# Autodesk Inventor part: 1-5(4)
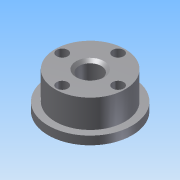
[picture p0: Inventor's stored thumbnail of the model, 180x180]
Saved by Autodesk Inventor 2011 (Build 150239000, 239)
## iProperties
Created: 2014-02
Part Number: 1-5(4)
Document SubType Name: Modeling
Designer: Administrator
Density: 1 g/cm^3
Author: Administrator
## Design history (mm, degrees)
sketch "草图1"
  geometry: C1 r 15 at (0, 0); 1 further point
  constraints: 1 centre point, 1 coincident
  dimensions: "d0" = 30 diameter of C1
extrude "拉伸1" new body sketch "草图1" distance "d1" = 3; taper "d2" = 0 deg
sketch "草图2"
  geometry: C1 r 15 at (0, 0) reference; C2 r 12.5 at (0, 0)
  constraints: 1 centre point, 1 coincident
  dimensions: "d3" = 25 diameter of C2
extrude "拉伸2" join sketch "草图2" distance "d4" = 10; taper "d5" = 0 deg
sketch "草图3"
  geometry: C1 r 12.5 at (0, 0) reference; C2 r 4 at (0, 0)
  constraints: 1 centre point, 1 coincident
  dimensions: "d6" = 8 diameter of C2
extrude "拉伸3" cut sketch "草图3" stored distance "d7" = 10; taper "d8" = 0 deg
chamfer "倒角1" distance "d9" = 1; stored, may be unused: second distance "d10" = 2, angle "d11" = 45 deg
chamfer "倒角2" distance "d12" = 1; stored, may be unused: second distance "d13" = 2, angle "d14" = 45 deg
sketch "草图4"
  geometry: C1 r 5 at (0, 0) reference; C2 r 1 at (0, 10); C3 r 1 at (0, -10); C4 r 1 at (10, 0); C5 r 1 at (-10, 0); A1 r 10 centre (0, 0) between (0, 10) and (0, -10)
  constraints: 5 centre point, 4 point on circle, 1 coincident
  dimensions: "d15" = 20 diameter of A1; "d16" = 2 diameter of C2; "d17" = 2 diameter of C3; "d18" = 2 diameter of C4; "d19" = 2 diameter of C5
extrude "拉伸4" cut sketch "草图4" stored distance "d20" = 10; taper "d21" = 0 deg
hole "Hole1" diameter "d24" = 4; stored, may be unused: countersink angle "d28" = 90 deg, drill point angle "d30" = 0 deg; dims "d22" = 10, "d23" = 10, "d25" = 6, "d26" = 4, "d27" = 2, "d29" = 3
pattern_circular "环形阵列1" dims angle "d32" = 360 deg
hole "Hole2" diameter "d36" = 4; stored, may be unused: countersink angle "d40" = 90 deg, drill point angle "d42" = 0 deg; dims "d34" = 10, "d35" = 10, "d37" = 6, "d38" = 4, "d39" = 2, "d41" = 3
pattern_circular "环形阵列2" dims angle "d44" = 360 deg
node "实体1"
